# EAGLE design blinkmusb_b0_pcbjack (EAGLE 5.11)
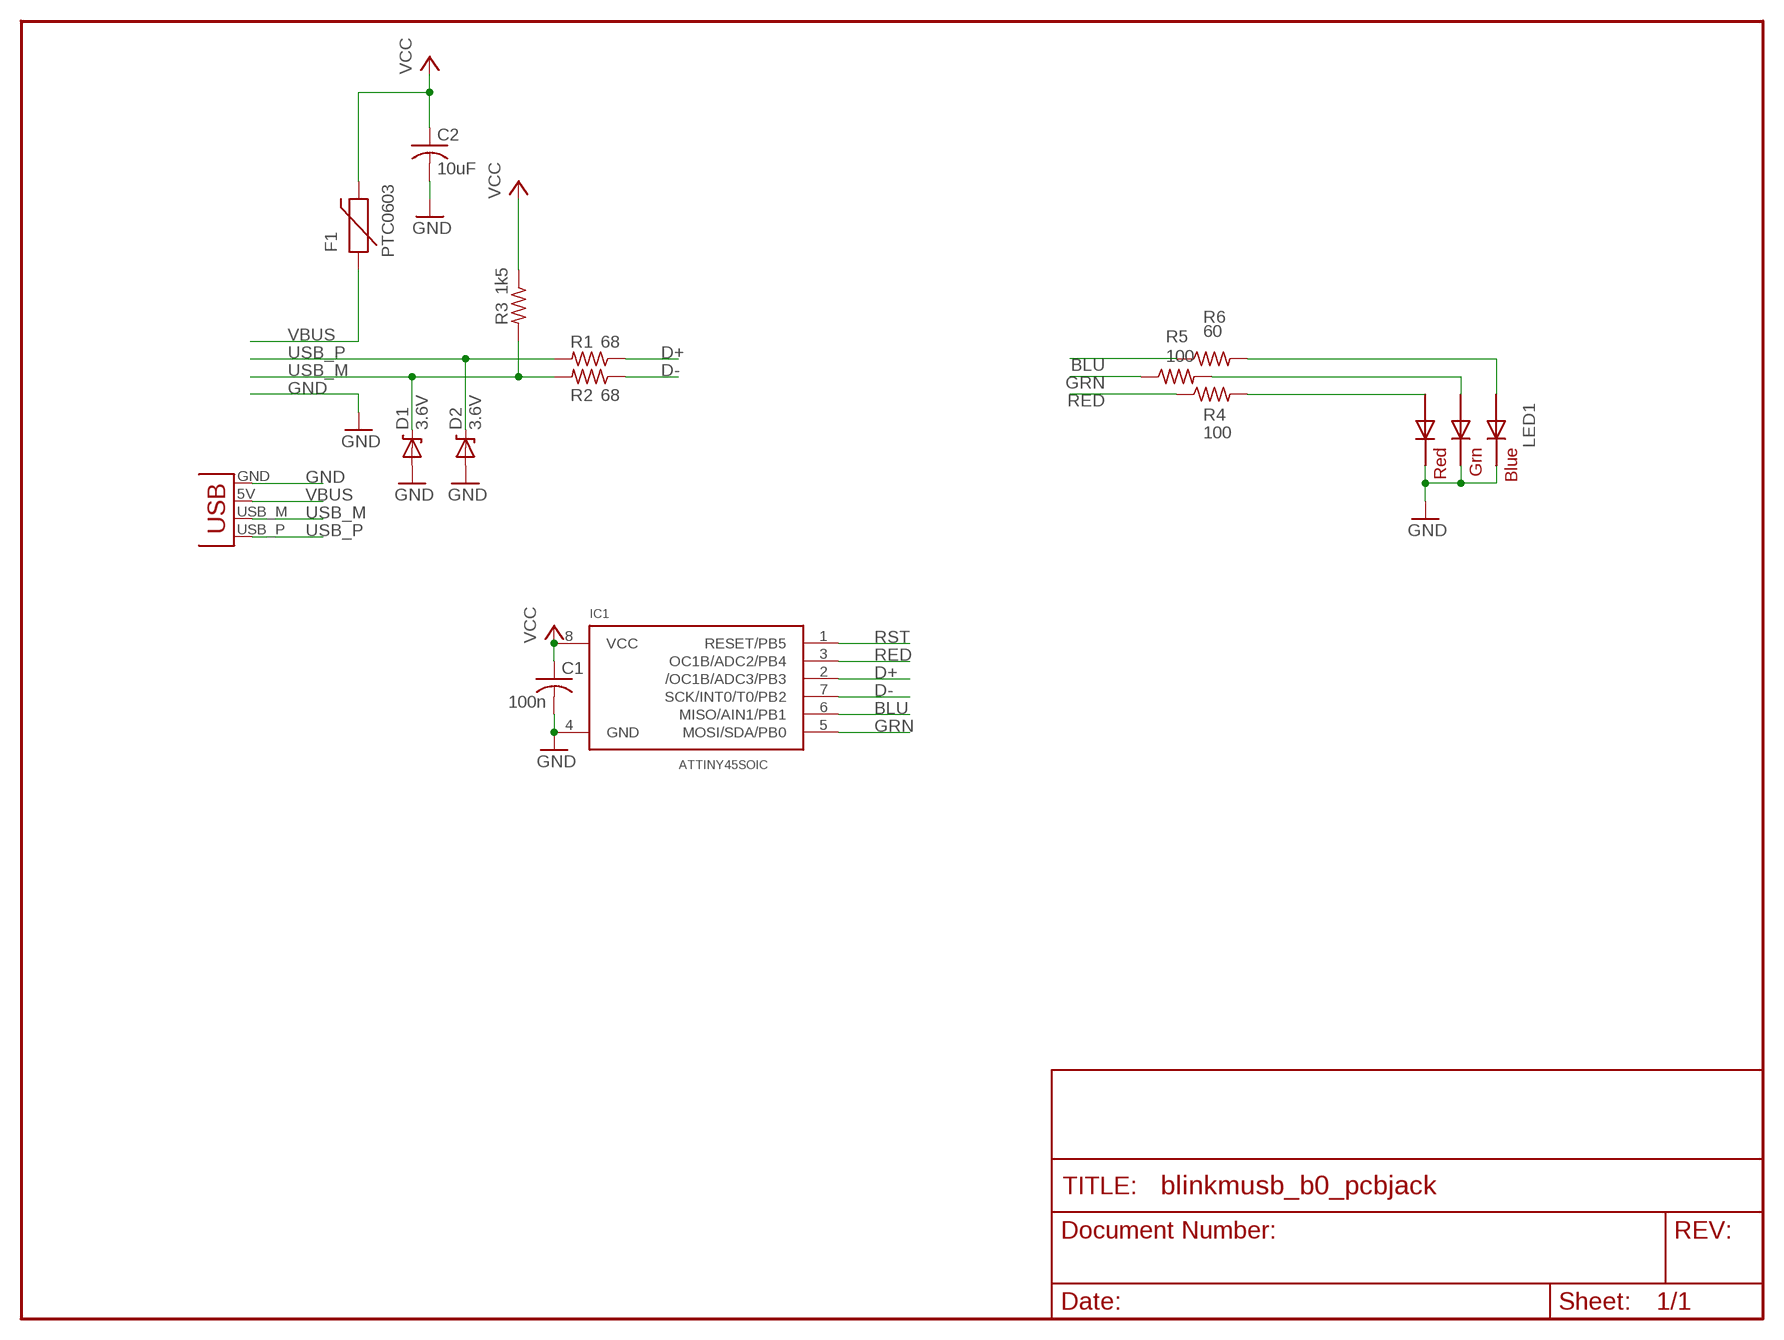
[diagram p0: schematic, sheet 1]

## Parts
C1  100n  C-USC0603  [C0603]
C2  10uF  C-USC0603  [C0603]
D1  3.6V  DIODE-ZENER-BZT52  [SOD-323]
D2  3.6V  DIODE-ZENER-BZT52  [SOD-323]
F1  PTC0603  [0603]
IC1  ATTINY45SOIC  [SO08-EIAJ]
LED1  RGBLED5050  [RGBLED5050]
R1  68  R-US_R0603  [R0603]
R2  68  R-US_R0603  [R0603]
R3  1k5  R-US_R0603  [R0603]
R4  100  R-US_R0603  [R0603]
R5  100  R-US_R0603  [R0603]
R6  60  R-US_R0603  [R0603]
X2  USBPCB  [USB-A-PCB]

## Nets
BLU: IC1.6(MISO/AIN1/PB1) R6.1
D+: IC1.2(/OC1B/ADC3/PB3) R1.1
D-: IC1.7(SCK/INT0/T0/PB2) R2.1
GND: C1.2 C2.2 D1.2(A) D2.2(A) IC1.4(GND) LED1.4(BLUE_C) LED1.5(RED_C) LED1.6(GREEN_C) X2.GND
GRN: IC1.5(MOSI/SDA/PB0) R5.1
RBLU: LED1.3(BLUE_A) R6.2
RED: IC1.3(OC1B/ADC2/PB4) R4.1
RGRN: LED1.1(GREEN_A) R5.2
RRED: LED1.2(RED_A) R4.2
RST: IC1.1(RESET/PB5)
USB_M: D1.1(C) R2.2 R3.2 X2.USB_M(D-)
USB_P: D2.1(C) R1.2 X2.USB_P(D+)
VBUS: F1.1 X2.5V(VBUS)
VCC: C1.1 C2.1 F1.2 IC1.8(VCC) R3.1

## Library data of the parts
C1 C2 = rcl:C-US: CAPACITOR, American symbol
D1 D2 = SparkFun-20110517:DIODE-ZENER: Zener Diode
F1 = SparkFun-20110517:PTC: Resettable Fuse PTC
IC1 = todstuff:ATTINY45
LED1 = adafruit-20120122:RGBLED: For 5050 RGB LEDs, the order of the LEDs may vary from one manufacturer to another!
R1-R6 = rcl:R-US_: RESISTOR, American symbol
X2 = SparkFun-20110517:USB: USB Connectors USB-B-PTH is fully proven SKU : PRT-00139 USB-miniB is fully proven SKU : PRT-00587 USB-A-PCB is untested. USB-A-H is throughly reviewed, but untested. Spark Fun Electronics SKU : PRT-00437 USB-B-SMT is throughly reviewed, but untested. Needs silkscreen touching up. USB-A-S has not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

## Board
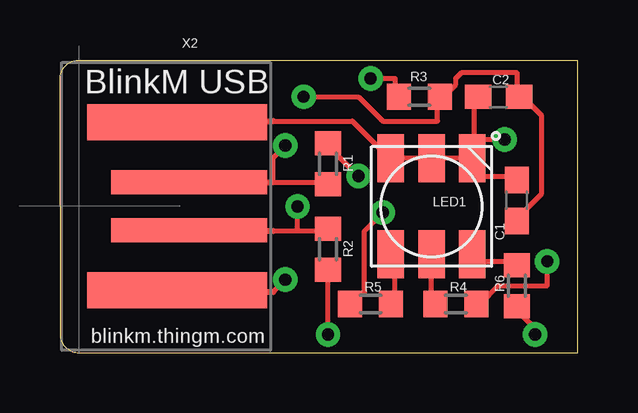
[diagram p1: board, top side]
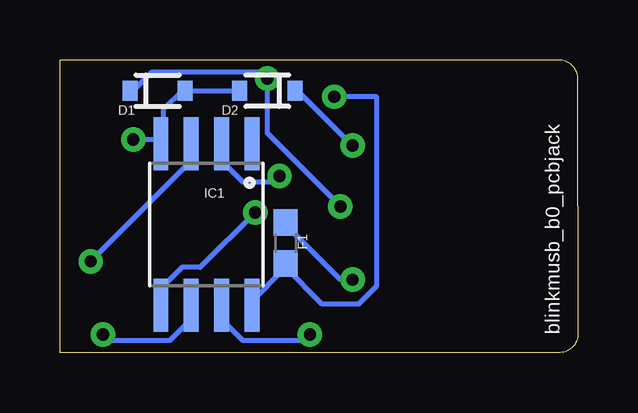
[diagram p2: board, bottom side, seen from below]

Size 21.6 x 12.2 mm. Coordinates in mm from the lower left corner, seen from the top.
Outline: 0.8,12.2 21.6,12.2 21.6,0 15.2,0 0.8,0 arc-90 0,0.8 0,6.1 0,11.4 arc-90 0.8,12.2
Copper layers (1*16): Top 0.035mm / dielectric 1.5mm / Bottom 0.035mm
Design rules "SparkFun": minimum track width 8mil, minimum drill 20mil, track to track 8mil, track to pad 8mil, pad to pad 8mil, via to via 8mil, smd to smd 8mil, copper to edge 10mil, drill to drill 8mil, minimum pad ring 12mil, minimum via ring 10mil, stop-mask expansion 4mil, vias tented up to drill 25mil, thermal gap 10mil
tRestrict: area 22.1,-0.8 to 30,12.7

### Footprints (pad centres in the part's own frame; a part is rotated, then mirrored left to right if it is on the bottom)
C0603 = smd 1.1 x 1: 1 -0.85,0; 2 0.85,0
SOD-323 = smd 0.63 x 0.83: 1 -1.15,0; 2 1.15,0
0603 = smd 1.1 x 1: 1 -0.85,0; 2 0.85,0
SO08-EIAJ = smd 0.61 x 2.21: 1 -1.905,-3.378; 2 -0.635,-3.378; 3 0.635,-3.378; 4 1.905,-3.378; 5 1.905,3.353; 6 0.635,3.353; 7 -0.635,3.353; 8 -1.905,3.353
RGBLED5050 = smd 2 x 1.1: 1 -2,1.7; 2 -2,0; 3 -2,-1.7; 4 2,-1.7; 5 2,0; 6 2,1.7
R0603 = smd 1 x 1.1: 1 -0.85,0; 2 0.85,0
USB-A-PCB = smd 7.5 x 1.5: 5V -0.2,-3.5; GND -0.2,3.5 | smd 6.5 x 1: USB_M 0.3,-1; USB_P 0.3,1

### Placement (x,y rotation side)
C1  19.05,6.35 90 top
C2  18.29,10.67 180 top
D1  17.53,10.92 0 bottom
D2  12.95,10.92 180 bottom
F1  12.19,4.57 270 bottom
IC1  15.49,5.33 180 bottom
LED1  15.49,6.1 90 top
R1  11.18,7.87 270 top
R2  11.18,4.32 90 top
R3  14.99,10.67 180 top
R4  16.51,2.03 180 top
R5  12.95,2.03 0 top
R6  19.05,2.79 90 top
X2  5.08,6.1 0 top

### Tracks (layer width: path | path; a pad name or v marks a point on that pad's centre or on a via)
BLU  (via drill 0.51)
  Top 0.203: v19.81,0.76 19.81,1.02 19.05,1.78 R6.1
  Bottom 0.203: v19.81,0.76 19.56,0.51 17.02,0.51 16.26,1.27 16.26,1.78 IC1.6
D+  (via drill 0.51)
  Top 0.203: v12.45,7.37 11.18,8.64 R1.1
  Bottom 0.203: v12.45,7.37 12.7,7.11 13.97,7.11 14.73,7.87 14.73,8.64 IC1.2
D-  (via drill 0.51)
  Top 0.203: v11.18,0.76 11.18,3.3 R2.1
  Bottom 0.203: v11.18,0.76 11.43,0.51 13.97,0.51 14.73,1.27 14.73,1.78 IC1.7
GND  (via drill 0.51)
  Top 0.203: 15.49,8.13 13.97,8.13 LED1.6 13.72,8.13 12.19,9.65 8.89,9.65 | 15.49,8.13 LED1.5 15.49,8.13 | C1.2 19.05,7.37 17.27,7.37 17.27,7.87 LED1.4 | 17.27,8.89 17.27,8.13 LED1.4 | 17.27,8.89 17.27,10.67 C2.2 | 15.49,8.13 17.02,8.13 LED1.4 | 17.27,8.89 v18.54,8.89 | LED1.4 17.27,8.89
  Top 0.254: X2.GND 4.94,9.65 8.89,9.65
  Bottom 0.203: D2.2 14.22,10.92 16.26,10.92 D1.2 16.51,10.92 17.27,10.16 17.27,8.89 IC1.4 17.53,8.89 v18.54,8.89
GRN  (via drill 0.51)
  Top 0.203: v13.46,5.84 12.7,5.08 12.7,2.54 12.19,2.03 R5.1
  Bottom 0.203: v13.46,5.84 15.75,3.56 16.51,3.56 17.27,2.79 17.27,2.03 IC1.5
RBLU
  Top 0.203: R6.2 19.05,3.81 17.27,3.81 17.27,4.06 LED1.3
RED  (via drill 0.51)
  Top 0.203: v20.32,3.81 20.32,2.79 18.29,2.79 17.53,2.03 R4.1
  Bottom 0.203: v20.32,3.81 16.26,7.87 16.26,8.64 IC1.3
RGRN
  Top 0.203: R5.2 13.97,2.03 13.97,4.06 LED1.1
RRED
  Top 0.203: R4.2 15.49,2.03 15.49,4.06 LED1.2
USB_M  (via drill 0.51)
  Top 0.203: 8.89,5.08 9.91,5.08 | 9.91,5.08 11.18,5.08 R2.2 | v12.95,11.43 13.97,11.43 13.97,10.67 R3.2 | 9.91,5.08 v9.91,6.1
  Top 0.254: X2.USB_M 5.4,5.08 8.89,5.08
  Bottom 0.203: D1.1 18.54,10.92 17.78,11.68 13.21,11.68 v12.95,11.43 12.95,9.14 v9.91,6.1
USB_P  (via drill 0.51)
  Top 0.203: v9.4,8.64 8.89,8.13 8.89,7.11 11.18,7.11 R1.2
  Top 0.254: X2.USB_P 5.4,7.11 8.89,7.11
  Bottom 0.203: v9.4,8.64 11.68,10.92 D2.1
VBUS  (via drill 0.51)
  Top 0.203: 8.89,2.54 v9.4,3.05
  Top 0.254: X2.5V 4.94,2.54 8.89,2.54
  Bottom 0.203: v9.4,3.05 9.91,3.05 12.19,5.33 F1.1
VCC  (via drill 0.51)
  Top 0.203: C1.1 19.05,5.59 20.07,6.6 20.07,9.91 19.3,10.67 C2.1 19.05,10.67 19.05,11.68 16.76,11.68 16.51,11.43 16.51,11.18 16,10.67 R3.1 15.75,10.67 15.75,9.65 13.46,9.65 12.45,10.67 v10.16,10.67
  Bottom 0.203: 12.19,3.56 13.72,2.03 IC1.8 | 12.19,3.56 F1.2 12.19,3.56 | 12.19,3.56 10.67,2.03 9.14,2.03 8.38,2.79 8.38,10.67 v10.16,10.67

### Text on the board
tPlace: BlinkM USB | blinkm.thingm.com
bPlace: blinkmusb_b0_pcbjack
